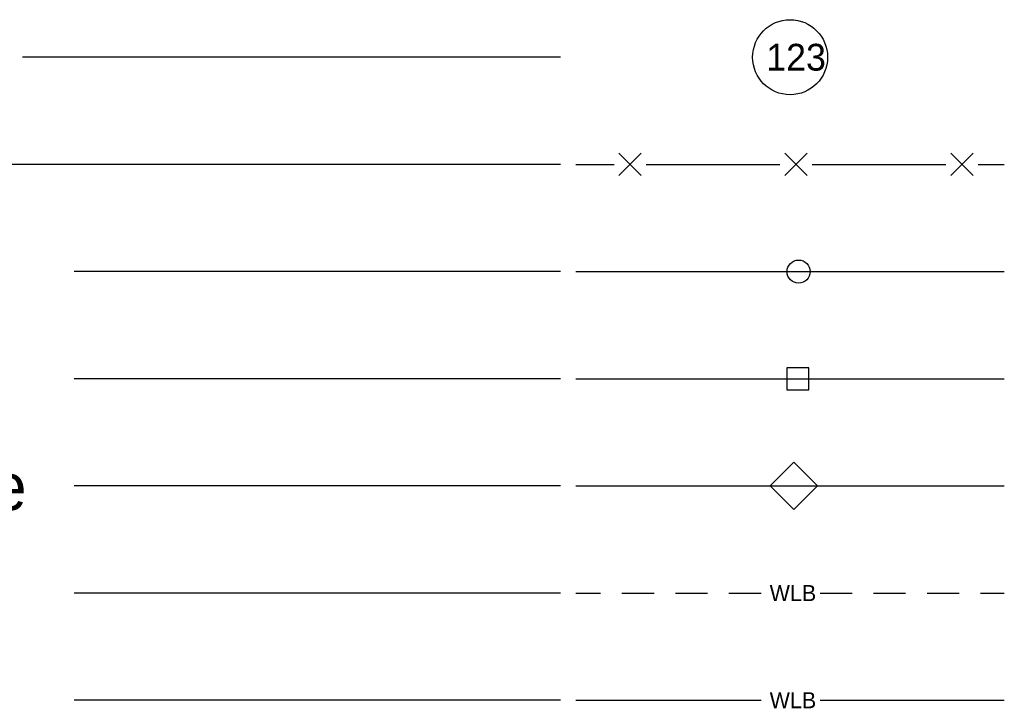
# Model space of a CAD drawing. Extents: x 0 to 3, y 0 to 1.83.
# Drawn here: x 0.3579 to 0.6672, y 1.1477 to 1.3638 of the extents above; entities that cross this region are included whole.
import ezdxf

# ---------------------------------------------------------------- set-up
doc = ezdxf.new("R2010")
doc.units = 0
doc.layers.add('Sheet_Symbology', color=7, linetype='Continuous')

msp = doc.modelspace()

# ---------------------------------------------------------------- linework, layer by layer
at = {"layer": 'Sheet_Symbology'}
for p, q in [((0.5278, 1.35204), (0.35882, 1.35204)), ((0.54608, 1.31487), (0.55315, 1.32194)), ((0.55315, 1.31487), (0.54608, 1.32194)), ((0.59821, 1.31487), (0.60527, 1.32194)), ((0.60527, 1.31487), (0.59821, 1.32194)), ((0.65034, 1.31487), (0.6574, 1.32194)), ((0.6574, 1.31487), (0.65034, 1.32194)), ((0.5278, 1.31841), (0.28378, 1.31841)), ((0.53263, 1.31841), (0.54457, 1.31841)), ((0.55466, 1.31841), (0.57568, 1.31841)), ((0.57568, 1.31841), (0.5967, 1.31841)), ((0.60679, 1.31841), (0.62781, 1.31841)), ((0.62781, 1.31841), (0.64883, 1.31841)), ((0.65892, 1.31841), (0.66716, 1.31841)), ((0.5278, 1.28477), (0.37505, 1.28477)), ((0.53263, 1.28477), (0.66716, 1.28477)), ((0.53263, 1.28477), (0.66716, 1.28477)), ((0.5278, 1.25114), (0.37505, 1.25114)), ((0.53263, 1.25114), (0.66716, 1.25114)), ((0.53263, 1.25114), (0.66716, 1.25114)), ((0.5278, 1.21751), (0.37505, 1.21751)), ((0.53263, 1.21751), (0.66716, 1.21751)), ((0.53263, 1.21751), (0.66716, 1.21751)), ((0.5278, 1.18388), (0.37505, 1.18388)), ((0.53263, 1.18388), (0.54032, 1.18388)), ((0.54705, 1.18388), (0.55714, 1.18388)), ((0.56387, 1.18388), (0.57396, 1.18388)), ((0.58068, 1.18388), (0.59077, 1.18388)), ((0.60927, 1.18388), (0.61936, 1.18388)), ((0.62608, 1.18388), (0.63617, 1.18388)), ((0.6429, 1.18388), (0.65299, 1.18388)), ((0.65972, 1.18388), (0.66716, 1.18388)), ((0.5278, 1.15025), (0.37505, 1.15025)), ((0.5278, 1.15025), (0.37505, 1.15025)), ((0.53263, 1.15025), (0.59077, 1.15025)), ((0.60927, 1.15025), (0.66716, 1.15025))]:
    msp.add_line(p, q, dxfattribs=at)
for points in [[(0.59884, 1.2477), (0.60574, 1.2477), (0.60574, 1.25459), (0.59884, 1.25459)], [(0.60107, 1.21011), (0.60847, 1.21751), (0.60107, 1.22499), (0.59367, 1.21751)]]:
    msp.add_lwpolyline(points, close=True, dxfattribs=at)
for centre, radius in [((0.59989, 1.35204), 0.01177), ((0.60254, 1.28477), 0.00362)]:
    msp.add_circle(centre, radius, dxfattribs=at)

# ---------------------------------------------------------------- texts
for s, height, p in [('123', 0.008408, (0.59237, 1.34783)), ('Proposed Barbed Wire Fence', 0.0147137, (0.10089, 1.20988)), ('WLB', 0.005045, (0.59346, 1.18136)), ('WLB', 0.005045, (0.59346, 1.14773))]:
    msp.add_text(s, height=height, dxfattribs=at).set_placement(p)

doc.saveas('drawing.dxf')
